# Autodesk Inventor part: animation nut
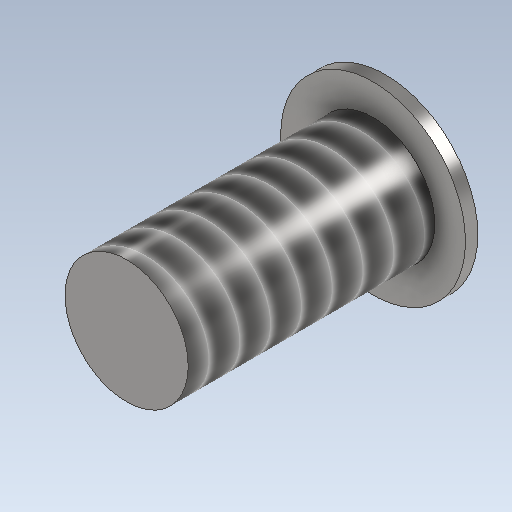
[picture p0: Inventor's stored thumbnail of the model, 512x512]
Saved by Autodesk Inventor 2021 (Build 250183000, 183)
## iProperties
Created: 2021-07
Part Number: animation nut
Material: Stainless Steel, Austenitic
Document SubType Name: Sheet Metal
Designer: user
Density: 8 g/cm^3
Sheet Metal Rule: Default_mm
Appearance: Semi-Polished
Author: user
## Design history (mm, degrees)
sketch "Sketch1"
  geometry: C1 r 0.75 at (0, 0); 1 further point
  constraints: 1 centre point, 1 coincident
  dimensions: "d0" = 1.5 diameter of C1
extrude "Extrusion1" new body sketch "Sketch1" distance "d1" = 0.1; taper "d2" = 0 deg
sketch "Sketch2"
  geometry: C1 r 0.5 at (0, 0); 1 further point
  constraints: 1 centre point, 1 coincident
  dimensions: "d3" = 1 diameter of C1
extrude "Extrusion2" join sketch "Sketch2" distance "d4" = 2; taper "d5" = 0 deg
thread "Thread1" dims "d6" = 9.9568, "d7" = 0
body "Solid1"
other parameters: "Thickness" = 0.5, "BendRadius" = 0.5 (= Thickness), "BendReliefWidth" = 0.5 (= Thickness), "BendReliefDepth" = 0.25 (= 0.5 x Thickness), "CornerReliefSize" = 2 (= 4 x Thickness), "SeamGap" = 0.01, "MinimumRemnant" = 1 (= 2 x Thickness), "TransitionRadius" = 0.5 (= BendRadius), "JacobiRadiusSize" = 0.5 (= BendRadius), "GapSize" = 0.5 (= Thickness)
